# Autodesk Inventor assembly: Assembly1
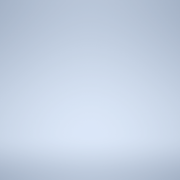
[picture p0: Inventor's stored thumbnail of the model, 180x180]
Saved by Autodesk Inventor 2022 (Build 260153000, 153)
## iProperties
Created: 2024-12
Part Number: Assembly1
Document SubType Name: Assembly
Designer: jsat7
Author: jsat7
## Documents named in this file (1)
- C:\Users\jsat7\OneDrive\デスクトップ\CAD 長田\Assembly1.iam
